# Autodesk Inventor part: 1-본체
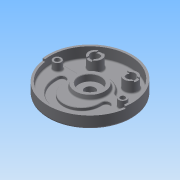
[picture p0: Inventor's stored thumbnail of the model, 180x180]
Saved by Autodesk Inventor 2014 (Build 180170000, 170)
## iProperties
Created: 2015-07
Part Number: 1-본체
Material: Generic
Document SubType Name: Modeling
Designer: Administrator
Density: 1 g/cm^3
Appearance: Default
Author: Administrator
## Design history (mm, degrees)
sketch "스케치1"
  geometry: C1 r 95 at (0, 0); 1 further point
  constraints: 1 centre point, 1 coincident
  dimensions: "d0" = 190 diameter of C1
extrude "돌출1" new body sketch "스케치1" distance "d1" = 32; taper "d2" = 0 deg
sketch "스케치2"
  geometry: C1 r 95 at (0, 0) reference; C2 r 90 at (0, 0)
  constraints: 1 centre point, 1 coincident
  dimensions: "d3" = 180 diameter of C2
extrude "돌출2" cut sketch "스케치2" distance "d4" = 18; taper "d5" = 0 deg
sketch "스케치3"
  geometry: L1 (45.033, 16)-(75.657, 16); L2 (-45.033, 16)-(-75.657, 16); A1 r 42 centre (0, 0) between (36.373, 21) and (-36.373, 21); A2 r 90 centre (0, 0) between (88.566, 16) and (-88.566, 16) reference; A3 r 90 centre (0, 0) between (85.114, 29.25) and (-85.114, 29.25); A4 r 10 centre (-75.657, 26) between (-85.114, 29.25) and (-75.657, 16); A5 r 10 centre (-45.033, 26) between (-45.033, 16) and (-36.373, 21); A6 r 10 centre (45.033, 26) between (36.373, 21) and (45.033, 16); A7 r 10 centre (75.657, 26) between (75.657, 16) and (85.114, 29.25); 3 further points
  constraints: 18 point on circle, 8 tangent, 6 centre point, 4 end point, 4 point on line, 3 equal radius, 2 coincident, 2 collinear, 1 horizontal
  dimensions: "d6" = 84 diameter of A1; "d8" = 16 distance from line of A3.centre L2; "d9" = 10 radius of A4
extrude "돌출3" cut sketch "스케치3" distance "d10" = 7; taper "d11" = 0 deg
sketch "스케치5"
  geometry: C1 r 35 at (0, 0); A1 r 90 centre (0, 0) between (-85.114, 29.25) and (85.114, 29.25) reference
  constraints: 1 centre point, 1 coincident
  dimensions: "d12" = 70 diameter of C1
extrude "돌출4" join sketch "스케치5" distance "d13" = 10; taper "d14" = -10 deg
sketch "스케치6"
  geometry: C1 r 15 at (-40, 52); C2 r 15 at (40, 52); A1 r 42 centre (0, 0) between (36.373, 21) and (-36.373, 21) reference
  constraints: 2 centre point, 1 equal radius, 1 horizontal alignment
  dimensions: "d15" = 80 distance of C2.centre C1.centre; "d16" = 30 diameter of C1; "d17" = 40 horizontal distance of A1.centre C1.centre; "d18" = 52 vertical distance of A1.centre C2.centre
extrude "돌출5" join sketch "스케치6" distance "d19" = 25; taper "d20" = 0 deg
sketch "스케치7"
  geometry: L1 (6, -21)-(-6, -21); L2 (-6, -21)-(-6, 21); L3 (-6, 21)-(6, 21); L4 (6, 21)-(6, -21); L5 (6, -21)-(-6, 21); L6 (-6, -21)-(6, 21); L7 (101, -6)-(59, -6); L8 (59, -6)-(59, 6); L9 (59, 6)-(101, 6); L10 (101, 6)-(101, -6); L11 (101, -6)-(59, 6); L12 (59, -6)-(101, 6); C1 r 15 at (0, 0) reference; C2 r 15 at (80, 0) reference; 1 further point
  constraints: 24 end point, 4 midpoint, 4 parallel, 4 perpendicular, 2 horizontal
  dimensions: "d21" = 12 distance of L2.end L3.end; "d22" = 42 distance of L3.end L1.start
extrude "돌출6" cut sketch "스케치7" distance "d23" = 3; taper "d24" = 0 deg
sketch "스케치8"
  geometry: C1 r 35 at (0, 0) reference; C2 r 9 at (-74, 0); C3 r 9 at (74, 0)
  constraints: 2 centre point, 2 horizontal alignment, 1 equal radius
  dimensions: "d25" = 18 diameter of C2; "d26" = 148 distance of C3.centre C2.centre; "d27" = 74 distance of C1.centre C2.centre
extrude "돌출7" join sketch "스케치8" distance "d28" = 18; taper "d29" = 0 deg
sketch "스케치9"
  geometry: L1 (-45.033, 16)-(-75.657, 16) reference; L2 (-59, -19)-(-59, -14); L3 (-41, -19)-(-41, -14); L4 (41, -19)-(41, -14); L5 (59, -19)-(59, -14); C1 r 35 at (0, 0) reference; A1 r 59 centre (0, -19) between (-59, -19) and (59, -19); A2 r 41 centre (0, -19) between (-41, -19) and (41, -19); A3 r 9 centre (-50, -14) between (-41, -14) and (-59, -14); A4 r 9 centre (50, -14) between (59, -14) and (41, -14)
  constraints: 8 end point, 8 point on circle, 8 tangent, 6 parallel, 4 centre point, 4 horizontal alignment, 1 perpendicular, 1 vertical alignment
  dimensions: "d30" = 19 distance of A1.centre C1.centre; "d31" = 59 radius of A1; "d32" = 41 radius of A2; "d33" = 5 distance of L5.start L5.end
extrude "돌출8" cut sketch "스케치9" distance "d34" = 7; taper "d35" = 0 deg
sketch "스케치10"
  geometry: C1 r 10 at (-40, 52); C2 r 10 at (40, 52); A1 r 15 centre (-40, 52) between (-46, 65.748) and (-46, 38.252) reference; A2 r 15 centre (40, 52) between (53.748, 58) and (26.252, 58) reference; 1 further point
  constraints: 2 centre point, 2 coincident, 1 equal radius
  dimensions: "d36" = 20 diameter of C1
extrude "돌출9" cut sketch "스케치10" stored distance "d37" = 7; taper "d38" = 0 deg
sketch "스케치11"
  geometry: C1 r 10 at (40, 52) reference; C2 r 10 at (-40, 52) reference; C3 r 95 at (0, 0) reference; C4 r 9 at (74, 0) reference; C5 r 9 at (-74, 0) reference; 2 further points
  constraints: 2 coincident
hole "구멍1" sketch "스케치11" at (-74, 0), (74, 0) diameter "d39" = 11; stored, may be unused: countersink angle "d43" = 90 deg, drill point angle "d45" = 118 deg; dims "d40" = 6, "d41" = 18, "d42" = 11, "d44" = 8
sketch "스케치12"
  geometry: C1 r 95 at (0, 0) reference; C2 r 68 at (0, 0)
  constraints: 1 centre point, 1 coincident, 1 other
  dimensions: "d55" = 136 diameter of C2
feature "엠보싱1" sketch "스케치12" dims "d56" = 0.5, "d57" = 0
sketch "스케치14"
  geometry: L1 (0, 0)-(94.075, -13.221); L2 (0, 0)-(-94.075, -13.221); C1 r 90 at (0, 0) reference; A1 r 95 centre (0, 0) between (94.075, -13.221) and (-94.075, -13.221) reference; 2 further points
  constraints: 4 end point, 4 point on circle, 2 horizontal alignment
  dimensions: "d61" = 8 deg dimension on C1.centre point (95, 0) L1.end; "d62" = 8 deg dimension on C1.centre point (-95, 0) L2.end
extrude "돌출10" cut sketch "스케치14" distance "d63" = 5; taper "d64" = 0 deg
sketch "스케치16"
  geometry: C1 r 95 at (0, 0) reference; C2 r 26 at (0, 0)
  constraints: 1 centre point, 1 coincident
  dimensions: "d71" = 52 diameter of C2
extrude "돌출12" join sketch "스케치16" distance "d72" = 12; taper "d73" = -15 deg
hole "구멍3" diameter "d76" = 23; stored, may be unused: countersink angle "d80" = 90 deg, drill point angle "d82" = 118 deg; dims "d74" = 10, "d75" = 10, "d77" = 6, "d78" = 50, "d79" = 15, "d81" = 8
chamfer "모따기2" distance "d83" = 1; stored, may be unused: second distance "d84" = 2, angle "d85" = 45 deg
fillet "모깎기1" dims "d86" = 1, "d87" = 0.3, "d88" = 5
fillet "모깎기2" dims "d89" = 3
node "솔리드1"
node "투영된 루프1"
node "투영된 루프2"
